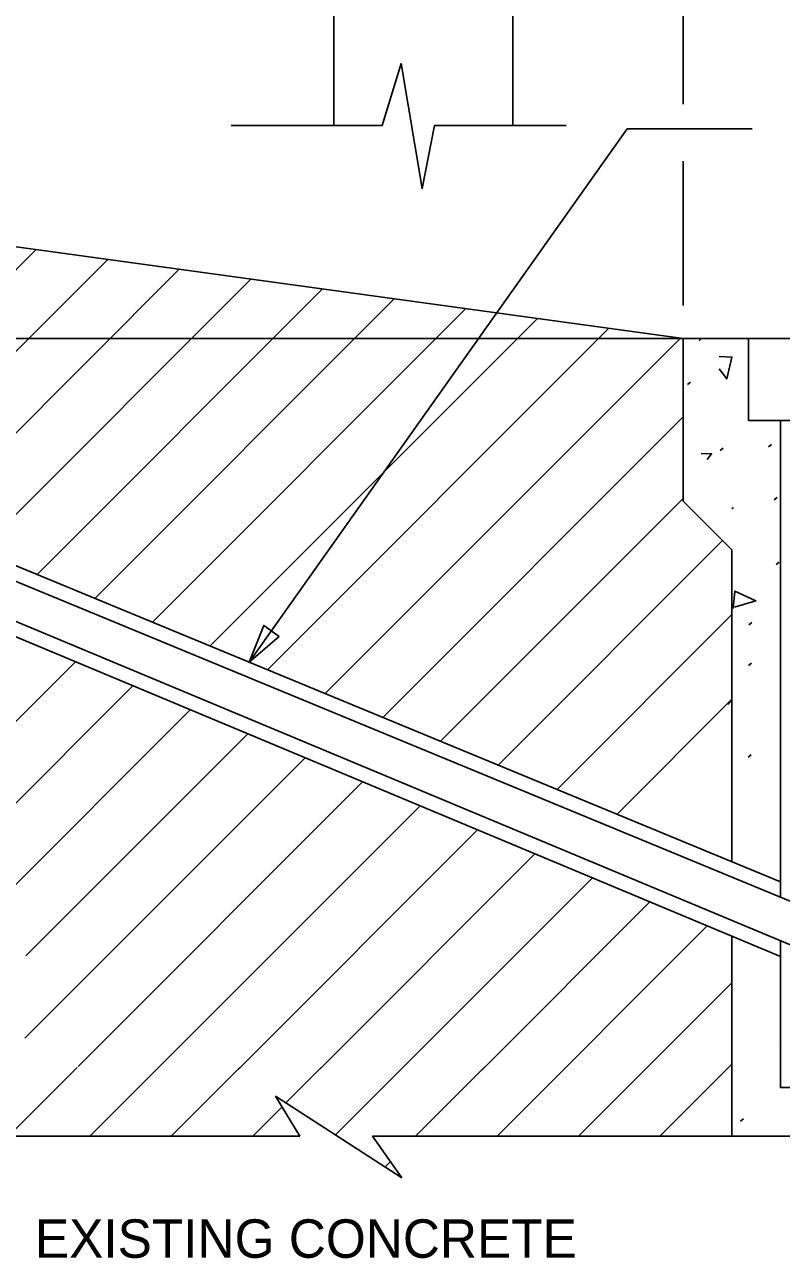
# Model space of a CAD drawing. Extents: x 3239 to 4230, y -4276 to -2494.
# Drawn here: x 3550.5 to 3609.7, y -4205.8 to -4109.5 of the extents above; entities that cross this region are included whole.
import ezdxf

# ---------------------------------------------------------------- set-up
doc = ezdxf.new("R2010")
doc.units = 0
doc.layers.add('2', color=7, linetype='Continuous')

msp = doc.modelspace()

# ---------------------------------------------------------------- linework, layer by layer
at = {"layer": '2'}
for p, q in [((3574.686, -4117.356), (3574.686, -4064.26)), ((3588.686, -4117.356), (3588.686, -4064.26)), ((3601.998, -4115.695), (3601.998, -4063.598)), ((3578.481, -4117.356), (3566.678, -4117.356)), ((3592.846, -4117.356), (3582.568, -4117.356)), ((3601.998, -4131.427), (3601.998, -4120.142)), ((3545.886, -4126.29), (3601.998, -4133.99)), ((3545.886, -4132.595), (3551.43, -4127.051)), ((3545.886, -4138.955), (3557.022, -4127.818)), ((3545.952, -4145.253), (3562.618, -4128.586)), ((3547, -4150.568), (3568.214, -4129.354)), ((3551.505, -4152.428), (3573.81, -4130.122)), ((3556.009, -4154.288), (3579.406, -4130.89)), ((3560.513, -4156.147), (3585.002, -4131.658)), ((3565.017, -4158.007), (3590.598, -4132.426)), ((3569.521, -4159.867), (3596.194, -4133.194)), ((3363.086, -4133.99), (3601.998, -4133.99)), ((3506.854, -4133.99), (3609.598, -4176.416)), ((3574.025, -4161.727), (3601.762, -4133.99)), ((3601.998, -4133.99), (3607.098, -4133.99)), ((3601.998, -4133.99), (3601.998, -4146.69)), ((3603.242, -4134.166), (3603.475, -4133.979)), ((3607.098, -4133.99), (3607.098, -4140.39)), ((3607.098, -4133.99), (3607.098, -4135.29)), ((3607.098, -4133.99), (3662.898, -4133.99)), ((3602.334, -4137.59), (3602.567, -4137.404)), ((3515.238, -4138.666), (3628.011, -4185.234)), ((3578.529, -4163.587), (3601.998, -4140.118)), ((3607.098, -4140.39), (3609.598, -4140.39)), ((3609.598, -4140.39), (3660.398, -4140.39)), ((3609.598, -4140.39), (3609.598, -4177.63)), ((3514.182, -4141.195), (3625.358, -4187.612)), ((3513.749, -4142.231), (3609.598, -4182.249)), ((3608.647, -4142.46), (3608.88, -4142.273)), ((3604.873, -4142.739), (3605.106, -4142.553)), ((3583.033, -4165.447), (3601.998, -4146.482)), ((3601.998, -4146.69), (3605.798, -4150.49)), ((3605.798, -4147.298), (3605.933, -4147.191)), ((3609.111, -4146.604), (3609.344, -4146.418)), ((3587.537, -4167.307), (3605.076, -4149.768)), ((3605.798, -4150.49), (3605.798, -4174.847)), ((3609.251, -4151.636), (3609.483, -4151.45)), ((3592.147, -4169.21), (3605.798, -4155.559)), ((3607.13, -4156.366), (3607.363, -4156.179)), ((3545.886, -4167.849), (3554.493, -4159.242)), ((3607.084, -4159.534), (3607.317, -4159.348)), ((3545.886, -4174.213), (3558.982, -4161.116)), ((3596.825, -4171.142), (3605.798, -4162.169)), ((3605.48, -4162.584), (3605.798, -4162.265)), ((3545.886, -4180.577), (3563.472, -4162.99)), ((3550.615, -4182.211), (3567.962, -4164.865)), ((3550.551, -4188.64), (3572.451, -4166.739)), ((3607.067, -4166.684), (3607.3, -4166.498)), ((3554.705, -4190.849), (3576.941, -4168.614)), ((3560.992, -4190.926), (3581.43, -4170.488)), ((3567.233, -4191.05), (3585.92, -4172.363)), ((3573.612, -4191.034), (3590.409, -4174.237)), ((3579.992, -4191.018), (3594.899, -4176.111)), ((3586.279, -4191.095), (3599.388, -4177.986)), ((3587.448, -4196.29), (3603.878, -4179.86)), ((3605.798, -4180.662), (3605.798, -4196.29)), ((3609.598, -4181.033), (3609.598, -4192.49)), ((3593.812, -4196.29), (3605.798, -4184.304)), ((3609.54, -4188.816), (3609.598, -4188.769)), ((3549.264, -4196.29), (3554.623, -4190.931)), ((3555.628, -4196.29), (3560.987, -4190.931)), ((3561.992, -4196.29), (3567.351, -4190.931)), ((3570.954, -4193.692), (3573.715, -4190.931)), ((3574.823, -4196.188), (3580.079, -4190.931)), ((3581.084, -4196.29), (3586.443, -4190.931)), ((3600.176, -4196.29), (3605.798, -4190.668)), ((3609.598, -4192.49), (3660.398, -4192.49)), ((3572.037, -4196.29), (3570.144, -4193.169)), ((3570.144, -4193.169), (3580.013, -4199.536)), ((3568.356, -4196.29), (3570.647, -4193.999)), ((3606.465, -4195.106), (3606.698, -4194.92)), ((3445.738, -4196.29), (3572.037, -4196.29)), ((3577.705, -4196.29), (3605.798, -4196.29)), ((3580.013, -4199.536), (3577.705, -4196.29)), ((3605.798, -4196.29), (3664.198, -4196.29)), ((3578.691, -4198.683), (3579.109, -4198.265))]:
    msp.add_line(p, q, dxfattribs=at)
for points in [[(3578.481, -4117.356), (3579.952, -4112.531), (3581.587, -4122.293), (3582.568, -4117.356)], [(3568.086, -4159.275), (3597.623, -4117.632), (3607.387, -4117.632)], [(3604.814, -4135.403), (3605.797, -4135.45), (3605.401, -4137.151), (3604.814, -4136.36)], [(3603.394, -4142.986), (3604.204, -4142.995), (3603.854, -4143.445)], [(3605.896, -4155.084), (3606.035, -4153.733), (3607.666, -4154.479), (3606.012, -4154.968)]]:
    msp.add_lwpolyline(points, dxfattribs=at)
msp.add_lwpolyline([(3570.433, -4157.262), (3568.086, -4159.275), (3569.21, -4156.394)], close=True, dxfattribs=at)

# ---------------------------------------------------------------- texts
msp.add_text('EXISTING CONCRETE', height=3, dxfattribs=at).set_placement((3551.332, -4205.781))

doc.saveas('drawing.dxf')
